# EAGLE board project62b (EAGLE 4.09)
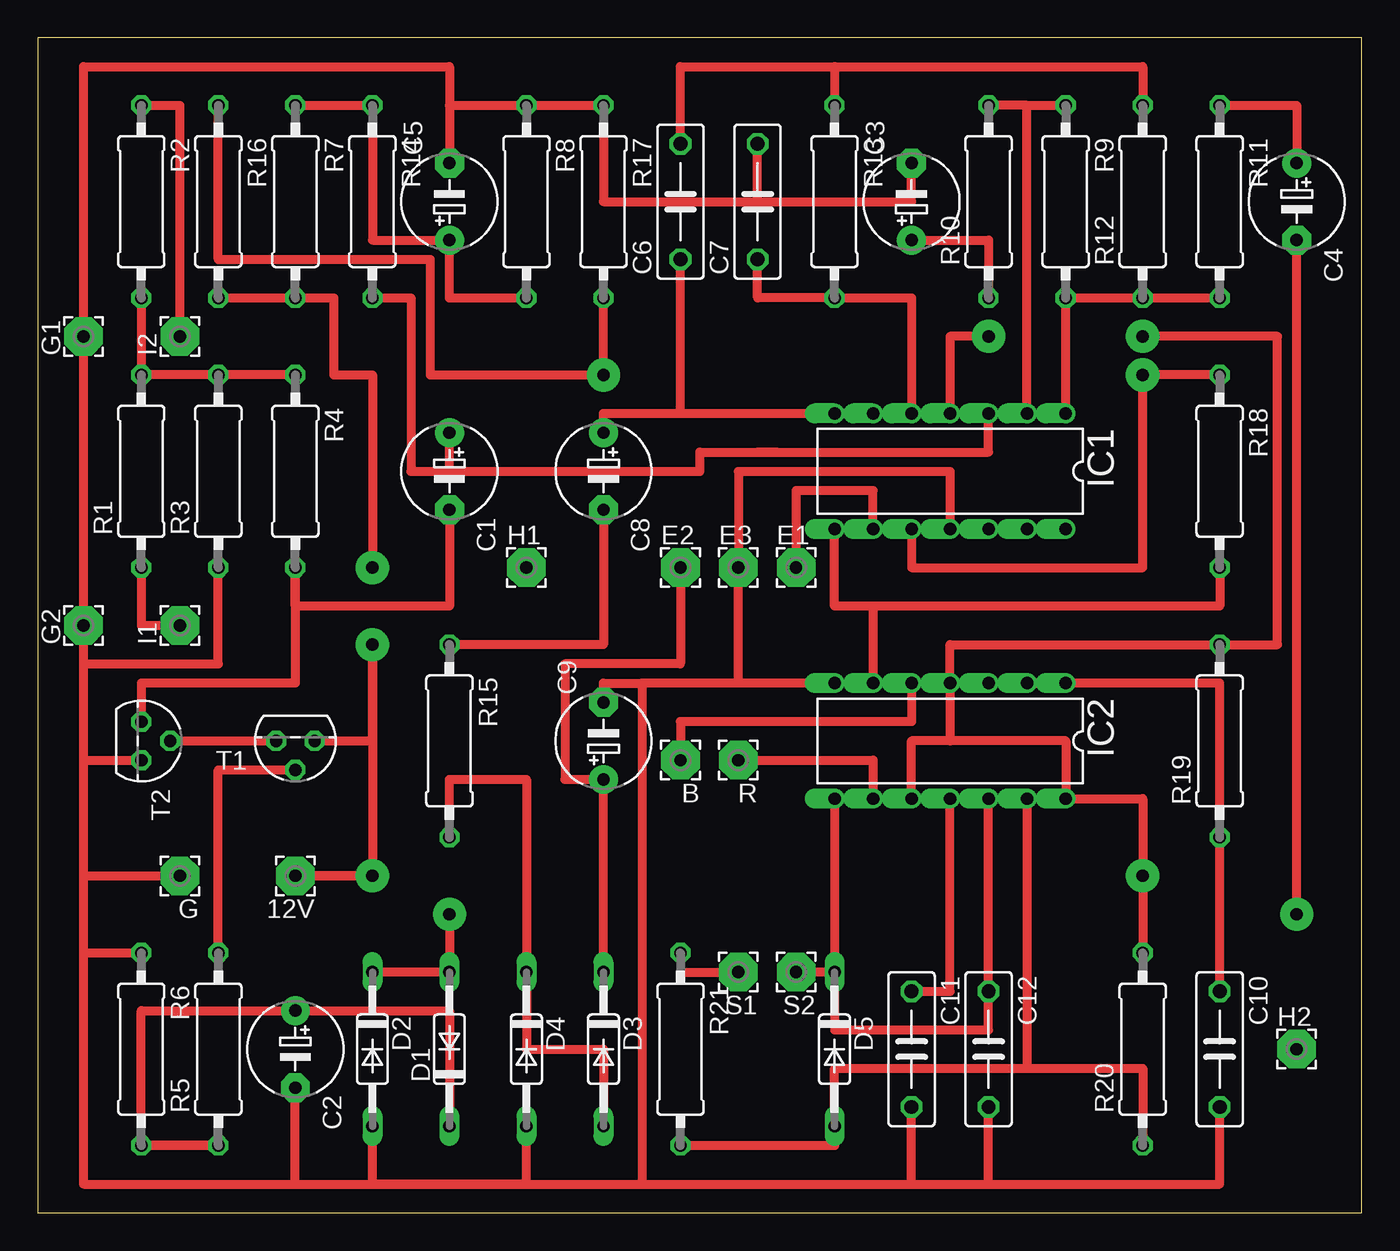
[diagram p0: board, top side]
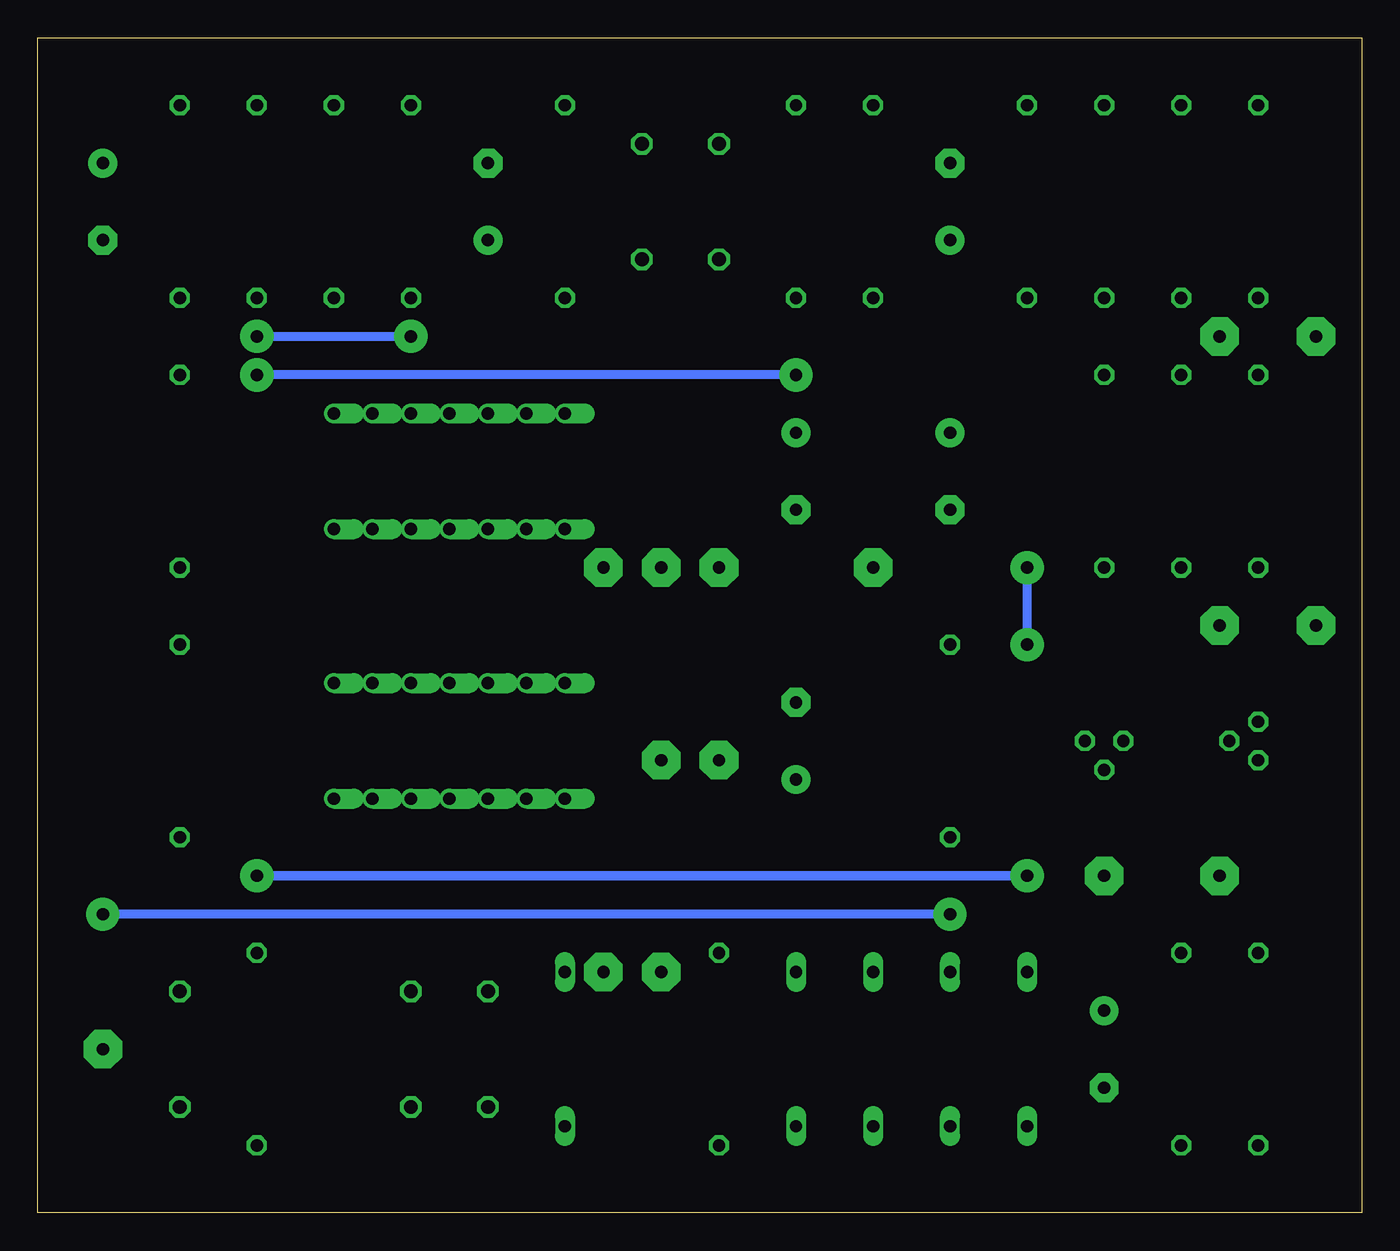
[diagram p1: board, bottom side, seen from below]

Size 87.3 x 77.46 mm. Coordinates in mm from the lower left corner, seen from the top.
Outline: 0,0 87.3,0 87.3,77.46 0,77.46 0,0
Copper layers used: Top, Bottom

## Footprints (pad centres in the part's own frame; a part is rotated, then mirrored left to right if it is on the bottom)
2,54/0,8 = drill 0.813 pad 2.54 octagon: 1 0,0
E5-6 = drill 0.813 pad 1.905 round: + -2.54,0 | drill 0.813 pad 1.905 octagon: - 2.54,0
C075-032X103 = drill 0.914 octagon: 1 -3.81,0; 2 3.81,0
DO35-10 = drill 0.813 long: A 5.08,0; C -5.08,0
DIL14 = drill 0.813 offset: 1 -7.62,-3.81; 2 -5.08,-3.81; 3 -2.54,-3.81; 4 0,-3.81; 5 2.54,-3.81; 6 5.08,-3.81; 7 7.62,-3.81; 8 7.62,3.81; 9 5.08,3.81; 10 2.54,3.81; 11 0,3.81; 12 -2.54,3.81; 13 -5.08,3.81; 14 -7.62,3.81
0309/12 = drill 0.813 octagon: 1 -6.35,0; 2 6.35,0
TO92 = drill 0.813 octagon: 1 1.27,0; 2 0,1.905; 3 -1.27,0

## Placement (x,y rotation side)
12V  [2,54/0,8]  16.98,22.22 180 top
B  [2,54/0,8]  42.38,29.84 180 top
C1  1u  [E5-6]  27.14,48.89 270 top
C2  47u  [E5-6]  16.98,10.79 270 top
C3  22u  [E5-6]  57.62,66.67 90 top
C4  22u  [E5-6]  83.02,66.67 270 top
C5  47u  [E5-6]  27.14,66.67 90 top
C6  22n  [C075-032X103]  42.38,66.67 90 top
C7  10n  [C075-032X103]  47.46,66.67 90 top
C8  22u  [E5-6]  37.3,48.89 270 top
C9  22u  [E5-6]  37.3,31.11 90 top
C10  22u  [C075-032X103]  77.94,10.79 270 top
C11  22n  [C075-032X103]  57.62,10.79 270 top
C12  22u  [C075-032X103]  62.7,10.79 270 top
D1  1N4148  [DO35-10]  27.14,10.79 90 top
D2  1N4148  [DO35-10]  22.06,10.79 270 top
D3  1N4148  [DO35-10]  37.3,10.79 270 top
D4  1N4148  [DO35-10]  32.22,10.79 270 top
D5  1N4148  [DO35-10]  52.54,10.79 270 top
E1  [2,54/0,8]  50,42.54 0 top
E2  [2,54/0,8]  42.38,42.54 0 top
E3  [2,54/0,8]  46.19,42.54 0 top
G  [2,54/0,8]  9.36,22.22 180 top
G1  [2,54/0,8]  3.01,57.78 90 top
G2  [2,54/0,8]  3.01,38.73 90 top
H1  [2,54/0,8]  32.22,42.54 0 top
H2  [2,54/0,8]  83.02,10.79 0 top
I1  [2,54/0,8]  9.36,38.73 90 top
I2  [2,54/0,8]  9.36,57.78 90 top
IC1  TL084_  [DIL14]  60.16,48.89 180 top
IC2  NE556N  [DIL14]  60.16,31.11 180 top
R  [2,54/0,8]  46.19,29.84 180 top
R1  270k  [0309/12]  6.82,48.89 90 top
R2  270k  [0309/12]  6.82,66.67 270 top
R3  47k  [0309/12]  11.9,48.89 90 top
R4  10k  [0309/12]  16.98,48.89 270 top
R5  10k  [0309/12]  11.9,10.79 90 top
R6  100k  [0309/12]  6.82,10.79 270 top
R7  100k  [0309/12]  16.98,66.67 270 top
R8  100k  [0309/12]  32.22,66.67 270 top
R9  27k  [0309/12]  67.78,66.67 270 top
R10  560  [0309/12]  62.7,66.67 90 top
R11  5k6  [0309/12]  77.94,66.67 270 top
R12  47k  [0309/12]  72.86,66.67 90 top
R13  47k  [0309/12]  52.54,66.67 270 top
R14  100k  [0309/12]  22.06,66.67 270 top
R15  560  [0309/12]  27.14,31.11 270 top
R16  180k  [0309/12]  11.9,66.67 270 top
R17  47k  [0309/12]  37.3,66.67 270 top
R18  270k  [0309/12]  77.94,48.89 270 top
R19  68k  [0309/12]  77.94,31.11 90 top
R20  2k2  [0309/12]  72.86,10.79 90 top
R21  4k7  [0309/12]  42.38,10.79 270 top
S1  [2,54/0,8]  46.19,15.87 180 top
S2  [2,54/0,8]  50,15.87 180 top
T1  BC549  [TO92]  16.98,31.11 180 top
T2  BC549  [TO92]  6.82,31.11 270 top

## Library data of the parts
12V B E1-E3 G G1 G2 H1 H2 I1 I2 R S1 S2 = wirepad
C1-C12 R1-R21 = rcl
D1-D5 = diode
IC1 IC2 = linear
T1 T2 = transistor-npn

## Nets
GND_: C2.- C3.- C5.- C7.2 C9.- C10.2 C11.2 C12.2 D2.A D4.A E3.1 G1.1 G2.1 G.1 IC1.11 IC2.7 R3.1 R6.1 R8.1 R17.1 T2.1
N$2: B.1 IC2.5
N$3: C6.1 C8.+ IC1.6 IC1.7
N$4: R1.2 R2.2 R3.2 R4.1
N$5: T1.1 T2.2
N$6: C1.- R4.2 T2.3
N$7: C1.+ IC1.3 R14.2
N$8: I1.1 R1.1
N$9: R21.1 S1.1
N$10: R5.2 T1.2
N$11: C8.- R15.1
N$12: I2.1 R2.1
N$13: C5.+ R7.1 R8.2 R14.1
N$14: C6.2 R12.2 R13.1
N$15: D3.A D4.C R15.2
N$16: C7.1 IC1.5 R13.2
N$17: C4.- D1.A D2.C
N$18: IC1.1 R9.2 R11.2 R12.1
N$19: IC1.2 R9.1 R10.2
N$20: C3.+ R10.1
N$22: C4.+ R11.1
N$23: C9.+ D3.C E2.1
N$24: D5.A IC2.13 R20.1 R21.2
N$25: E1.1 IC1.9
N$26: 12V.1 IC1.4 IC2.4 IC2.10 IC2.14 R7.2 R16.2 R19.2 R20.2 T1.3
N$27: IC1.10 R16.1 R17.2 R18.1
N$28: C12.1 D5.C IC2.8 IC2.12 S2.1
N$29: C2.+ D1.C R5.1 R6.2
N$30: IC1.8 IC2.6 R18.2
N$31: C11.1 IC2.11
N$34: C10.1 IC2.1 IC2.2 R19.1
N$35: IC2.9 R.1

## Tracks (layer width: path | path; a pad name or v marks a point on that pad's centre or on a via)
GND_
  Top 0.61: 47.46,66.67 C7.2 | 3.01,29.84 T2.1 | 3.01,17.14 R6.1 | 16.98,1.9 C2.- | 22.06,1.9 D2.A | 27.14,73.02 C5.- | 27.14,73.02 R8.1 R17.1 | 3.01,17.14 3.01,22.22 | 3.01,1.9 3.01,17.14 | 62.7,1.9 77.94,1.9 C10.2 | 62.7,1.9 C12.2 | 57.62,1.9 C11.2 | 3.01,1.9 16.98,1.9 | 16.98,1.9 22.06,1.9 | 32.22,1.9 22.06,1.9 | 32.22,1.9 D4.A | 3.01,22.22 3.01,29.84 | 3.01,29.84 3.01,36.19 | C3.- 57.62,66.67 47.46,66.67 | 47.46,66.67 37.3,66.67 R17.1 | 27.14,73.02 R17.1 | 3.01,36.19 11.9,36.19 R3.1 | 27.14,73.02 27.14,75.56 3.01,75.56 G1.1 G2.1 3.01,36.19 | 3.01,22.22 G.1 | 3.01,1.9 3.01,22.22 | 3.01,1.9 32.22,1.9 | 32.22,1.9 39.84,1.9 | IC1.11 60.16,48.89 46.19,48.89 E3.1 46.19,34.92 | IC2.7 46.19,34.92 | C9.- 37.3,34.92 39.84,34.92 | 46.19,34.92 39.84,34.92 | 39.84,34.92 39.84,1.9 | 39.84,1.9 57.62,1.9 | 57.62,1.9 62.7,1.9
N$2
  Top 0.61: IC2.5 57.62,32.38 42.38,32.38 B.1
N$3
  Top 0.61: 42.38,52.7 C6.1 | C8.+ 37.3,52.7 42.38,52.7 | 42.38,52.7 IC1.7 IC1.6
N$4
  Top 0.61: R4.1 R3.2 R1.2 R2.2
N$5
  Top 0.61: T2.2 T1.1
N$6
  Top 0.61: C1.- 27.14,40 16.98,40 R4.2 16.98,34.92 6.82,34.92 T2.3
N$7
  Top 0.61: IC1.3 62.7,50.16 48.73,50.16 | 48.73,50.16 47.46,50.16 | 48.73,50.16 43.65,50.16 43.65,48.89 27.14,48.89 | R14.2 24.6,60.32 24.6,48.89 27.14,48.89 | 27.14,48.89 C1.+
N$8
  Top 0.61: R1.1 6.82,38.73 I1.1
N$9
  Top 0.61: R21.1 42.38,15.87 S1.1
N$10
  Top 0.61: R5.2 11.9,29.2 T1.2
N$11
  Top 0.61: C8.- 37.3,37.46 R15.1
N$12
  Top 0.61: R2.1 9.36,73.02 I2.1
N$13
  Top 0.61: R8.2 27.14,60.32 C5.+ 22.06,64.13 R14.1 R7.1
N$14
  Top 0.61: 52.54,75.56 72.86,75.56 R12.2 | 52.54,75.56 R13.1 | 52.54,75.56 42.38,75.56 C6.2
N$15
  Top 0.61: R15.2 27.14,28.57 32.22,28.57 D4.C 32.22,10.79 37.3,10.79 D3.A
N$16
  Top 0.61: C7.1 47.46,60.32 R13.2 57.62,60.32 IC1.5
N$17  (via drill 0.81 pad 2.18)
  Top 0.61: D2.C D1.A v27.14,19.68 | v83.02,19.68 C4.-
  Bottom 0.61: v27.14,19.68 v83.02,19.68
N$18
  Top 0.61: R9.2 R12.1 | R9.2 R12.1 | IC1.1 R9.2 | R9.2 R12.1 | R12.1 R11.2
N$19
  Top 0.61: 65.24,73.02 R10.2 | IC1.2 65.24,73.02 | 65.24,73.02 R9.1
N$20
  Top 0.61: C3.+ 62.7,64.13 R10.1
N$22
  Top 0.61: R11.1 83.02,73.02 C4.+
N$23
  Top 0.61: D3.C C9.+ 34.76,28.57 34.76,36.19 42.38,36.19 E2.1
N$24
  Top 0.61: D5.A 52.54,9.52 | R20.1 72.86,9.52 65.24,9.52 | 52.54,9.52 65.24,9.52 | IC2.13 65.24,9.52 | R21.2 52.54,4.44 52.54,9.52
N$25
  Top 0.61: IC1.9 55.08,47.62 50,47.62 E1.1
N$26  (via drill 0.81 pad 2.18)
  Top 0.61: R16.2 R7.2 19.52,60.32 19.52,55.24 22.06,55.24 v22.06,42.54 | v62.7,57.78 60.16,57.78 IC1.4 | v72.86,57.78 81.75,57.78 81.75,37.46 R19.2 60.16,37.46 IC2.4 60.16,31.11 | IC2.10 57.62,31.11 60.16,31.11 | 60.16,31.11 67.78,31.11 IC2.14 72.86,27.3 v72.86,22.22 R20.2 | T1.3 22.06,31.11 v22.06,37.46 v22.06,22.22 | v22.06,22.22 12V.1 v22.06,22.22
  Bottom 0.61: v22.06,22.22 v72.86,22.22 | v72.86,57.78 v62.7,57.78 | v22.06,22.22 v72.86,22.22 | v72.86,22.22 v22.06,22.22 | v22.06,42.54 v22.06,37.46
N$27  (via drill 0.81 pad 2.18)
  Top 0.61: R16.1 11.9,62.86 25.87,62.86 25.87,55.24 v37.3,55.24 R17.2 | IC1.10 57.62,42.54 72.86,42.54 v72.86,55.24 R18.1
  Bottom 0.61: v37.3,55.24 v72.86,55.24 v37.3,55.24
N$28
  Top 0.61: C12.1 IC2.12 C12.1 | D5.C IC2.8 D5.C | D5.C 52.54,12.06 62.7,12.06 C12.1 | D5.C S2.1
N$29
  Top 0.61: R6.2 R5.1 R6.2 | R6.2 6.82,13.33 C2.+ 27.14,13.33 D1.C
N$30
  Top 0.61: 55.08,40 IC2.6 | 55.08,40 52.54,40 IC1.8 | R18.2 77.94,40 55.08,40
N$31
  Top 0.61: C11.1 60.16,14.6 IC2.11
N$34
  Top 0.61: IC2.1 IC2.2 77.94,34.92 R19.1 C10.1
N$35
  Top 0.61: R.1 55.08,29.84 IC2.9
